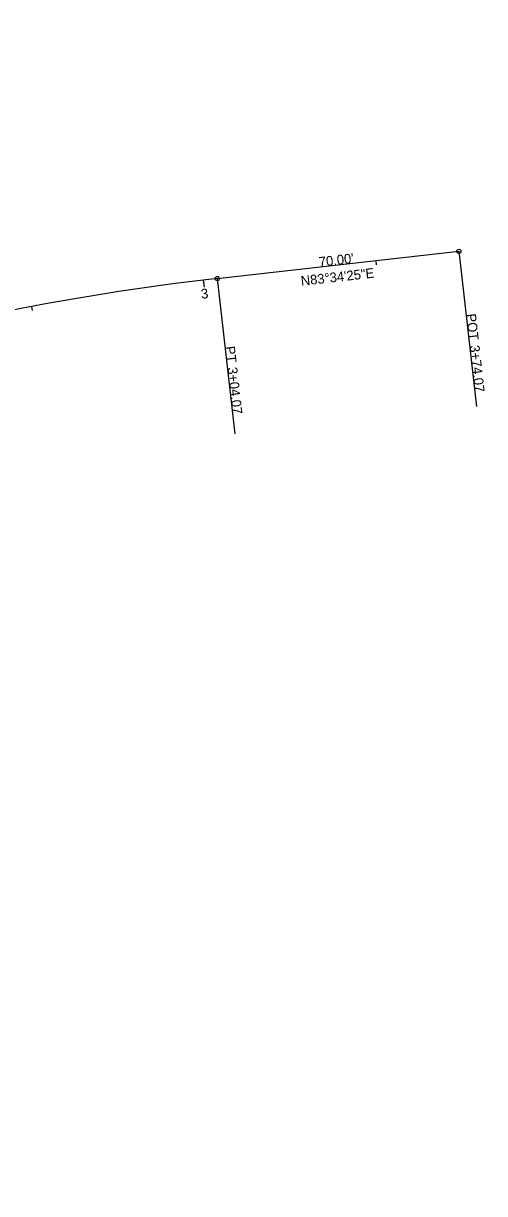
# Model space of a CAD drawing. Extents: x 1492452 to 1496782, y 514026 to 517659.
# Drawn here: x 1494779 to 1494911.7, y 514788.1 to 515125.3 of the extents above; entities that cross this region are included whole.
import ezdxf

# ---------------------------------------------------------------- set-up
doc = ezdxf.new("R2010")
doc.units = 0
for name, color, linetype in [('Default', 7, 'Continuous'), ('DR_X_Ditch', 7, 'Continuous'), ('DT_X_Break_Line', 7, 'Continuous'), ('DT_X_TIN_Hull', 7, 'Continuous'), ('DT_X_Void', 7, 'Continuous'), ('GE_X_Cells', 7, 'Continuous'), ('RD_X_Cells', 7, 'Continuous'), ('RD_X_GR_Lt', 7, 'Continuous'), ('SV_X_Random_Point', 7, 'Continuous'), ('UT_X_Electric_Cells', 7, 'Continuous'), ('UT_X_Misc_Cells', 7, 'Continuous'), ('UT_X_Water', 7, 'Continuous'), ('UT_X_Water_Cells', 7, 'Continuous')]:
    doc.layers.add(name, color=color, linetype=linetype)

msp = doc.modelspace()

# ---------------------------------------------------------------- linework, layer by layer
at = {"layer": 'Default'}
msp.add_line((1494834.78, 515051.74), (1494904.34, 515059.58), dxfattribs=at)
for centre, radius, start, end in [((1486425.91, 524780.42), 12277.67, 302.444021, 313.600151), ((1494914.94, 514340.04), 716.2, 96.42645, 117.27596)]:
    msp.add_arc(centre, radius, start, end, dxfattribs=at)
at = {"layer": 'DT_X_TIN_Hull'}
for p, q in [((1494880.42, 515056.88), (1494880.56, 515055.69)), ((1494830.74, 515051.28), (1494830.97, 515049.29)), ((1494781.33, 515043.67), (1494781.55, 515042.49))]:
    msp.add_line(p, q, dxfattribs=at)
at = {"layer": 'DT_X_Void'}
for p, q in [((1494904.34, 515059.58), (1494909.38, 515014.86)), ((1494834.78, 515051.74), (1494839.82, 515007.02))]:
    msp.add_line(p, q, dxfattribs=at)
for centre in [(1494904.34, 515059.58), (1494834.78, 515051.74)]:
    msp.add_circle(centre, 0.6, dxfattribs=at)
at = {"layer": 'GE_X_Cells'}
msp.add_line((1494834.78, 515051.74), (1494904.34, 515059.58), dxfattribs=at)
for centre, radius, start, end in [((1486425.91, 524780.42), 12277.67, 302.444021, 313.600151), ((1494914.94, 514340.04), 716.2, 96.42645, 117.27596)]:
    msp.add_arc(centre, radius, start, end, dxfattribs=at)
at = {"layer": 'RD_X_Cells'}
for p, q in [((1494904.34, 515059.58), (1494909.38, 515014.86)), ((1494834.78, 515051.74), (1494839.82, 515007.02))]:
    msp.add_line(p, q, dxfattribs=at)
for centre in [(1494904.34, 515059.58), (1494834.78, 515051.74)]:
    msp.add_circle(centre, 0.6, dxfattribs=at)
at = {"layer": 'UT_X_Misc_Cells'}
for p, q in [((1494904.34, 515059.58), (1494909.38, 515014.86)), ((1494834.78, 515051.74), (1494839.82, 515007.02))]:
    msp.add_line(p, q, dxfattribs=at)
for centre in [(1494904.34, 515059.58), (1494834.78, 515051.74)]:
    msp.add_circle(centre, 0.6, dxfattribs=at)
at = {"layer": 'UT_X_Water_Cells'}
msp.add_line((1494830.74, 515051.28), (1494830.88, 515050.08), dxfattribs=at)

# ---------------------------------------------------------------- texts
at = {"layer": 'DR_X_Ditch'}
msp.add_text("70.00'", height=2.8, rotation=6.4264, dxfattribs=at).set_placement((1494864.19, 515055.1))
at = {"layer": 'DT_X_Break_Line'}
msp.add_text('N83°34\'25"E', height=2.8, rotation=6.4264, dxfattribs=at).set_placement((1494858.99, 515049.64))
at = {"layer": 'DT_X_TIN_Hull'}
msp.add_text('3', height=2.8, rotation=6.752, dxfattribs=at).set_placement((1494830.28, 515045.88))
at = {"layer": 'DT_X_Void'}
for s, p in [('POT', (1494906.43, 515041.46)), ('PT', (1494837.04, 515032.11)), ('3+74.07', (1494907.45, 515032.39)), ('3+04.07', (1494837.72, 515026.06))]:
    msp.add_text(s, height=2.8, rotation=276.4264, dxfattribs=at).set_placement(p)
at = {"layer": 'RD_X_Cells'}
for s, p in [('POT', (1494906.43, 515041.46)), ('PT', (1494837.04, 515032.11)), ('3+74.07', (1494907.45, 515032.39)), ('3+04.07', (1494837.72, 515026.06))]:
    msp.add_text(s, height=2.8, rotation=276.4264, dxfattribs=at).set_placement(p)
at = {"layer": 'RD_X_GR_Lt'}
msp.add_text("70.00'", height=2.8, rotation=6.4264, dxfattribs=at).set_placement((1494864.19, 515055.1))
at = {"layer": 'SV_X_Random_Point'}
msp.add_text('N83°34\'25"E', height=2.8, rotation=6.4264, dxfattribs=at).set_placement((1494858.99, 515049.64))
at = {"layer": 'UT_X_Electric_Cells'}
msp.add_text('N83°34\'25"E', height=2.8, rotation=6.4264, dxfattribs=at).set_placement((1494858.99, 515049.64))
at = {"layer": 'UT_X_Misc_Cells'}
for s, p in [('POT', (1494906.43, 515041.46)), ('PT', (1494837.04, 515032.11)), ('3+74.07', (1494907.45, 515032.39)), ('3+04.07', (1494837.72, 515026.06))]:
    msp.add_text(s, height=2.8, rotation=276.4264, dxfattribs=at).set_placement(p)
at = {"layer": 'UT_X_Water'}
msp.add_text("70.00'", height=2.8, rotation=6.4264, dxfattribs=at).set_placement((1494864.19, 515055.1))

doc.saveas('drawing.dxf')
